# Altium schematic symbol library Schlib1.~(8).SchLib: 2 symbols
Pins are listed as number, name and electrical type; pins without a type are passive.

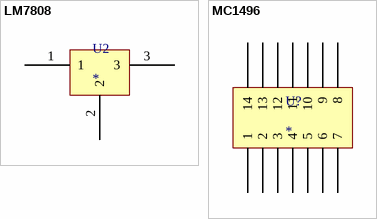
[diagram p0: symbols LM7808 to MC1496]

## LM7808
designator U2
pins: 1, 2, 3

## MC1496
designator U?
pins: 1, 2, 3, 4, 5, 6, 7, 8, 9, 10, 11, 12, 13, 14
